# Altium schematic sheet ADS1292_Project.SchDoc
size 431 x 279 mm; Date: Not shown in title block; ApprovedBy: Not shown in title block; CheckedBy: Not shown in title block; Author: Not shown in title block; CompanyName: Not shown in title block; Engineer: Not shown in title block; Organization: Not shown in title block; Address1: Not shown in title block; Address2: Not shown in title block; Address3: Not shown in title block; Address4: Not shown in title block; DocumentNumber: 1; Revision: Use project parameter SCH_Rev; SheetNumber: 2; SheetTotal: 3; PageSetup: Record=PageOptions¦CenterHorizontal=True¦CenterVertical=True¦PrintScale=1.00¦XCorrection=1.00¦YCorrection=1.00¦PrintKind=0¦BorderSize=5000000¦LeftOffset=0¦BottomOffset=0¦Orientation=2¦PaperLength=1000¦PaperWidth=1000¦Scale=100¦PaperSource=15¦PrintQuality=600¦MediaType=1¦DitherType=10¦PaperKind=Letter¦PrintScaleMode=1
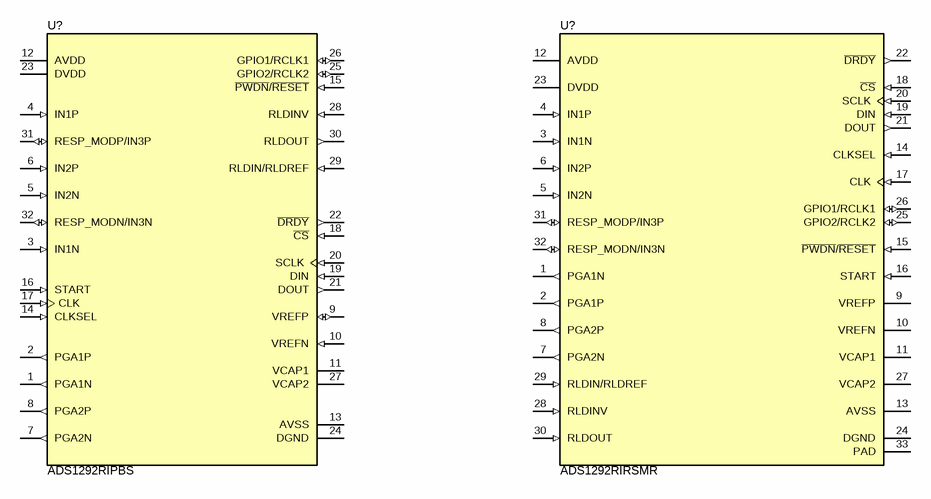
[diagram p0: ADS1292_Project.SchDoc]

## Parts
(Parts that share a designator on the sheet are numbered #1, #2 ... from top to bottom, then left to right.)
U?#1  ADS1292RIPBS  [PBS0032A_N]
U?#2  ADS1292RIRSMR  [RSM0032B]

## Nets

Not connected (* = marked no-connect by the designer): U?#1 1(PGA1N) 2(PGA1P) 3(IN1N) 4(IN1P) 5(IN2N) 6(IN2P) 7(PGA2N) 8(PGA2P) 9(VREFP) 10(VREFN) 11(VCAP1) 12(AVDD) 13(AVSS) 14(CLKSEL) 15(~{PWDN}/~{RESET}) 16(START) 17(CLK) 18(~{CS}) 19(DIN) 20(SCLK) 21(DOUT) 22(~{DRDY}) 23(DVDD) 24(DGND) 25(GPIO2/RCLK2) 26(GPIO1/RCLK1) 27(VCAP2) 28(RLDINV) 29(RLDIN/RLDREF) 30(RLDOUT) 31(RESP_MODP/IN3P) 32(RESP_MODN/IN3N); U?#2 1(PGA1N) 2(PGA1P) 3(IN1N) 4(IN1P) 5(IN2N) 6(IN2P) 7(PGA2N) 8(PGA2P) 9(VREFP) 10(VREFN) 11(VCAP1) 12(AVDD) 13(AVSS) 14(CLKSEL) 15(~{PWDN}/~{RESET}) 16(START) 17(CLK) 18(~{CS}) 19(DIN) 20(SCLK) 21(DOUT) 22(~{DRDY}) 23(DVDD) 24(DGND) 25(GPIO2/RCLK2) 26(GPIO1/RCLK1) 27(VCAP2) 28(RLDINV) 29(RLDIN/RLDREF) 30(RLDOUT) 31(RESP_MODP/IN3P) 32(RESP_MODN/IN3N) 33(PAD)

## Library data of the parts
U?#1 = ADS1292RIPBS: Low-Power, 2-Channel, 24-Bit Analog Front-End for Biopotential Measurement, PBS0032A; Manufacturer: Texas Instruments; SymbolCreator: Altium; SizeArea_mm2: 49; SizeAreaWB_mm2: 81; SizeX_mm: 7; SizeZ_mm: 1.2; CompType: IC; U/M: EA
U?#2 = ADS1292RIRSMR: Low-Power, 2-Channel, 24-Bit Analog Front-End for Biopotential Measurements, RSM0032B; Alternate PartNumber: ADS1292RIRSMT; Manufacturer: Texas Instruments; SymbolCreator: Altium; SizeArea_mm2: 16; SizeAreaWB_mm2: 25; SizeX_mm: 4; SizeZ_mm: 1; CompType: IC; U/M: EA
